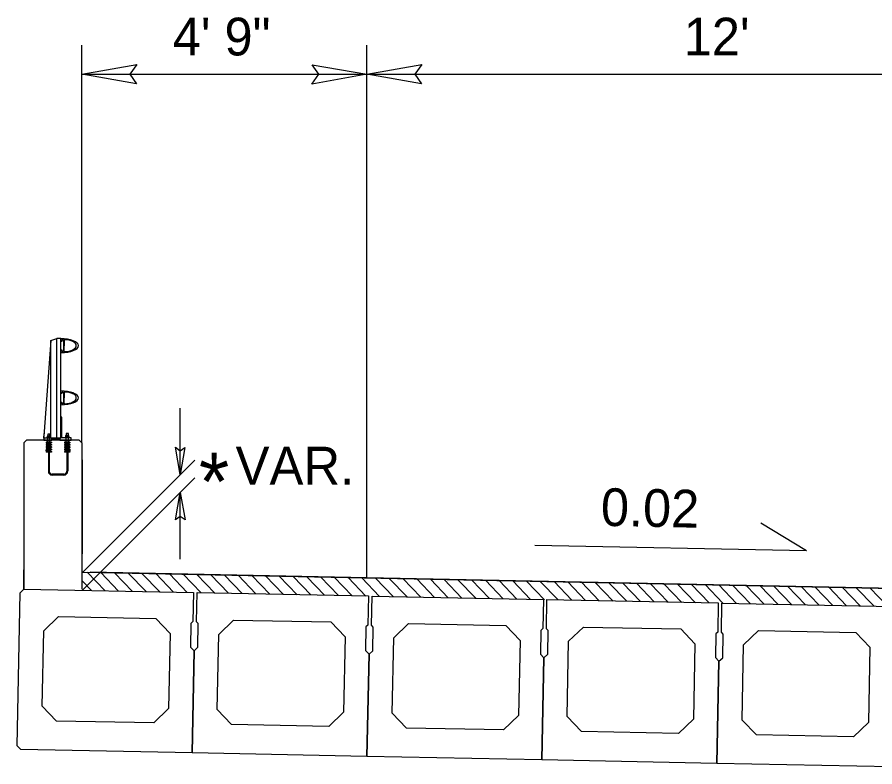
# Model space of a CAD drawing. Extents: x 573771 to 574316, y -53454 to -53190.
# Drawn here: x 574112.51 to 574141.94, y -53351.54 to -53325.81 of the extents above; entities that cross this region are included whole.
import ezdxf

# ---------------------------------------------------------------- set-up
doc = ezdxf.new("R2010")
doc.units = 0
for name, color, linetype in [('Default', 7, 'Continuous'), ('Typical Pavement Slope CELL', 7, 'Continuous'), ('Typical Pavement Slope Information CELL', 7, 'Continuous'), ('Typical Shoulder Slope CELL', 7, 'Continuous'), ('Typical Terminator CELL', 7, 'Continuous'), ('Typical Text Grade Point CELL', 7, 'Continuous')]:
    doc.layers.add(name, color=color, linetype=linetype)

msp = doc.modelspace()

# ---------------------------------------------------------------- linework, layer by layer
at = {"layer": 'Default'}
for p, q in [((574113.663, -53336.907), (574113.87, -53336.839)), ((574114.007, -53336.839), (574113.87, -53336.839)), ((574113.87, -53340.257), (574113.87, -53336.839)), ((574114.007, -53340.257), (574114.007, -53336.839)), ((574113.663, -53336.907), (574113.425, -53340.189)), ((574113.663, -53340.257), (574113.663, -53336.907)), ((574114.121, -53336.896), (574114.121, -53337.082)), ((574114.121, -53337.267), (574114.121, -53337.082)), ((574114.121, -53338.688), (574114.121, -53338.873)), ((574114.121, -53339.059), (574114.121, -53338.873)), ((574112.741, -53340.414), (574112.83, -53340.326)), ((574114.642, -53340.326), (574112.83, -53340.326)), ((574113.425, -53340.257), (574113.425, -53340.189)), ((574113.431, -53340.151), (574113.431, -53340.091)), ((574113.557, -53340.409), (574113.557, -53340.257)), ((574113.636, -53340.119), (574113.558, -53340.119)), ((574113.558, -53340.119), (574113.558, -53340.183)), ((574113.635, -53340.409), (574113.635, -53340.257)), ((574113.636, -53340.183), (574113.636, -53340.119)), ((574114.187, -53340.391), (574114.187, -53340.24)), ((574114.269, -53340.101), (574114.191, -53340.101)), ((574114.191, -53340.101), (574114.191, -53340.166)), ((574114.269, -53340.166), (574114.269, -53340.101)), ((574114.273, -53340.391), (574114.273, -53340.24)), ((574114.642, -53340.326), (574114.731, -53340.414)), ((574112.741, -53340.414), (574112.741, -53345.438)), ((574113.686, -53340.391), (574113.504, -53340.391)), ((574113.686, -53340.412), (574113.504, -53340.412)), ((574113.579, -53340.472), (574113.504, -53340.472)), ((574113.579, -53340.492), (574113.504, -53340.492)), ((574113.579, -53340.553), (574113.504, -53340.553)), ((574113.579, -53340.573), (574113.504, -53340.573)), ((574113.579, -53340.633), (574113.504, -53340.633)), ((574113.579, -53340.653), (574113.504, -53340.653)), ((574113.579, -53340.432), (574113.544, -53340.432)), ((574113.579, -53340.452), (574113.544, -53340.452)), ((574113.579, -53340.513), (574113.544, -53340.513)), ((574113.579, -53340.533), (574113.544, -53340.533)), ((574113.579, -53340.593), (574113.544, -53340.593)), ((574113.579, -53340.613), (574113.544, -53340.613)), ((574113.579, -53340.674), (574113.544, -53340.674)), ((574113.61, -53340.432), (574113.579, -53340.432)), ((574113.579, -53340.432), (574113.579, -53341.395)), ((574113.645, -53340.432), (574113.61, -53340.432)), ((574113.61, -53340.432), (574113.61, -53341.395)), ((574113.645, -53340.452), (574113.61, -53340.452)), ((574113.686, -53340.472), (574113.61, -53340.472)), ((574113.686, -53340.492), (574113.61, -53340.492)), ((574113.645, -53340.513), (574113.61, -53340.513)), ((574113.645, -53340.533), (574113.61, -53340.533)), ((574113.686, -53340.553), (574113.61, -53340.553)), ((574113.686, -53340.573), (574113.61, -53340.573)), ((574113.645, -53340.593), (574113.61, -53340.593)), ((574113.645, -53340.613), (574113.61, -53340.613)), ((574113.686, -53340.633), (574113.61, -53340.633)), ((574113.686, -53340.653), (574113.61, -53340.653)), ((574113.645, -53340.674), (574113.61, -53340.674)), ((574114.318, -53340.391), (574114.136, -53340.391)), ((574114.318, -53340.412), (574114.136, -53340.412)), ((574114.212, -53340.472), (574114.136, -53340.472)), ((574114.212, -53340.492), (574114.136, -53340.492)), ((574114.212, -53340.553), (574114.136, -53340.553)), ((574114.212, -53340.573), (574114.136, -53340.573)), ((574114.212, -53340.633), (574114.136, -53340.633)), ((574114.212, -53340.653), (574114.136, -53340.653)), ((574114.212, -53340.432), (574114.177, -53340.432)), ((574114.212, -53340.452), (574114.177, -53340.452)), ((574114.212, -53340.513), (574114.177, -53340.513)), ((574114.212, -53340.533), (574114.177, -53340.533)), ((574114.212, -53340.593), (574114.177, -53340.593)), ((574114.212, -53340.613), (574114.177, -53340.613)), ((574114.212, -53340.674), (574114.177, -53340.674)), ((574114.243, -53340.432), (574114.212, -53340.432)), ((574114.212, -53340.432), (574114.212, -53341.395)), ((574114.278, -53340.432), (574114.243, -53340.432)), ((574114.243, -53340.432), (574114.243, -53341.395)), ((574114.278, -53340.452), (574114.243, -53340.452)), ((574114.318, -53340.472), (574114.243, -53340.472)), ((574114.318, -53340.492), (574114.243, -53340.492)), ((574114.278, -53340.513), (574114.243, -53340.513)), ((574114.278, -53340.533), (574114.243, -53340.533)), ((574114.318, -53340.553), (574114.243, -53340.553)), ((574114.318, -53340.573), (574114.243, -53340.573)), ((574114.278, -53340.593), (574114.243, -53340.593)), ((574114.278, -53340.613), (574114.243, -53340.613)), ((574114.318, -53340.633), (574114.243, -53340.633)), ((574114.318, -53340.653), (574114.243, -53340.653)), ((574114.278, -53340.674), (574114.243, -53340.674)), ((574114.731, -53340.414), (574114.731, -53345.438)), ((574113.579, -53340.714), (574113.504, -53340.714)), ((574113.579, -53340.734), (574113.504, -53340.734)), ((574113.579, -53340.694), (574113.544, -53340.694)), ((574113.645, -53340.694), (574113.61, -53340.694)), ((574113.686, -53340.714), (574113.61, -53340.714)), ((574113.686, -53340.734), (574113.61, -53340.734)), ((574114.212, -53340.714), (574114.136, -53340.714)), ((574114.212, -53340.734), (574114.136, -53340.734)), ((574114.212, -53340.694), (574114.177, -53340.694)), ((574114.278, -53340.694), (574114.243, -53340.694)), ((574114.318, -53340.714), (574114.243, -53340.714)), ((574114.318, -53340.734), (574114.243, -53340.734)), ((574114.743, -53340.998), (574114.743, -53344.231)), ((574114.116, -53341.491), (574113.707, -53341.491)), ((574114.116, -53341.522), (574113.707, -53341.522)), ((574112.744, -53344.584), (574112.744, -53342.453)), ((574112.743, -53345.438), (574112.743, -53344.771)), ((574114.756, -53344.856), (574182.408, -53346.215)), ((574115.526, -53345.497), (574114.914, -53344.86)), ((574115.992, -53345.506), (574115.379, -53344.869)), ((574116.463, -53345.516), (574115.851, -53344.878)), ((574116.934, -53345.525), (574116.322, -53344.888)), ((574117.405, -53345.535), (574116.793, -53344.897)), ((574117.877, -53345.544), (574117.264, -53344.907)), ((574118.348, -53345.554), (574117.736, -53344.916)), ((574118.819, -53345.563), (574118.207, -53344.926)), ((574119.291, -53345.573), (574118.678, -53344.935)), ((574119.762, -53345.582), (574119.15, -53344.945)), ((574120.233, -53345.591), (574119.621, -53344.954)), ((574120.705, -53345.601), (574120.092, -53344.964)), ((574121.176, -53345.61), (574120.564, -53344.973)), ((574121.647, -53345.62), (574121.035, -53344.982)), ((574122.119, -53345.629), (574121.506, -53344.992)), ((574122.59, -53345.639), (574121.978, -53345.001)), ((574123.061, -53345.648), (574122.449, -53345.011)), ((574123.532, -53345.658), (574122.92, -53345.02)), ((574124.004, -53345.667), (574123.391, -53345.03)), ((574124.475, -53345.677), (574123.863, -53345.039)), ((574124.946, -53345.686), (574124.334, -53345.049)), ((574125.418, -53345.696), (574124.805, -53345.058)), ((574125.889, -53345.705), (574125.277, -53345.068)), ((574126.36, -53345.714), (574125.748, -53345.077)), ((574126.832, -53345.724), (574126.219, -53345.087)), ((574115.064, -53345.488), (574114.753, -53345.163)), ((574127.303, -53345.733), (574126.691, -53345.096)), ((574127.774, -53345.743), (574127.162, -53345.105)), ((574128.246, -53345.752), (574127.633, -53345.115)), ((574128.717, -53345.762), (574128.105, -53345.124)), ((574129.188, -53345.771), (574128.576, -53345.134)), ((574129.659, -53345.781), (574129.047, -53345.143)), ((574130.131, -53345.79), (574129.518, -53345.153)), ((574130.602, -53345.8), (574129.99, -53345.162)), ((574131.073, -53345.809), (574130.461, -53345.172)), ((574131.545, -53345.819), (574130.932, -53345.181)), ((574132.016, -53345.828), (574131.404, -53345.191)), ((574132.487, -53345.837), (574131.875, -53345.2)), ((574132.959, -53345.847), (574132.346, -53345.21)), ((574133.43, -53345.856), (574132.818, -53345.219)), ((574133.901, -53345.866), (574133.289, -53345.228)), ((574134.373, -53345.875), (574133.76, -53345.238)), ((574134.844, -53345.885), (574134.232, -53345.247)), ((574135.315, -53345.894), (574134.703, -53345.257)), ((574135.787, -53345.904), (574135.174, -53345.266)), ((574136.258, -53345.913), (574135.646, -53345.276)), ((574136.729, -53345.923), (574136.117, -53345.285)), ((574137.2, -53345.932), (574136.588, -53345.295)), ((574137.672, -53345.942), (574137.059, -53345.304)), ((574138.143, -53345.951), (574137.531, -53345.314)), ((574138.614, -53345.96), (574138.002, -53345.323)), ((574139.086, -53345.97), (574138.473, -53345.333)), ((574139.557, -53345.979), (574138.945, -53345.342)), ((574140.028, -53345.989), (574139.416, -53345.351)), ((574140.5, -53345.998), (574139.887, -53345.361)), ((574140.971, -53346.008), (574140.359, -53345.37)), ((574141.442, -53346.017), (574140.83, -53345.38)), ((574141.914, -53346.027), (574141.301, -53345.389)), ((574142.385, -53346.036), (574141.773, -53345.399))]:
    msp.add_line(p, q, dxfattribs=at)
for points in [[(574114.007, -53337.318), (574114.007, -53337.23), (574114.044, -53337.23), (574114.044, -53337.244), (574114.04, -53337.244), (574114.04, -53337.282), (574114.099, -53337.282), (574114.106, -53337.224), (574114.106, -53337.082), (574114.106, -53336.939), (574114.099, -53336.881), (574114.04, -53336.881), (574114.04, -53336.919), (574114.044, -53336.919), (574114.044, -53336.934), (574114.007, -53336.934), (574114.007, -53336.844)], [(574114.007, -53339.11), (574114.007, -53339.021), (574114.044, -53339.021), (574114.044, -53339.036), (574114.04, -53339.036), (574114.04, -53339.073), (574114.099, -53339.073), (574114.106, -53339.016), (574114.106, -53338.873), (574114.106, -53338.73), (574114.099, -53338.673), (574114.04, -53338.673), (574114.04, -53338.71), (574114.044, -53338.71), (574114.044, -53338.725), (574114.007, -53338.725), (574114.007, -53338.636)], [(574114.357, -53340.326), (574114.357, -53340.24), (574114.041, -53340.24), (574114.041, -53339.539), (574114.007, -53339.539), (574114.007, -53340.257), (574113.441, -53340.257), (574113.441, -53340.207), (574113.425, -53340.207), (574113.425, -53340.326), (574113.698, -53340.326), (574113.698, -53340.278), (574113.973, -53340.278), (574113.973, -53340.326), (574114.357, -53340.326)], [(574113.674, -53340.258), (574113.674, -53340.243), (574113.597, -53340.243), (574113.519, -53340.243), (574113.519, -53340.258)], [(574113.654, -53340.243), (574113.654, -53340.193), (574113.645, -53340.183), (574113.549, -53340.183), (574113.539, -53340.193), (574113.539, -53340.243), (574113.654, -53340.243), (574113.616, -53340.243), (574113.616, -53340.193), (574113.626, -53340.183), (574113.616, -53340.193), (574113.607, -53340.183), (574113.587, -53340.183), (574113.577, -53340.193), (574113.577, -53340.243), (574113.577, -53340.193), (574113.567, -53340.183)], [(574114.309, -53340.241), (574114.309, -53340.225), (574114.231, -53340.225), (574114.153, -53340.225), (574114.153, -53340.241)], [(574114.288, -53340.226), (574114.288, -53340.176), (574114.279, -53340.166), (574114.182, -53340.166), (574114.172, -53340.176), (574114.172, -53340.226), (574114.288, -53340.226), (574114.249, -53340.226), (574114.249, -53340.176), (574114.259, -53340.166), (574114.249, -53340.176), (574114.24, -53340.166), (574114.22, -53340.166), (574114.21, -53340.176), (574114.21, -53340.226), (574114.21, -53340.176), (574114.201, -53340.166)], [(574113.504, -53340.391), (574113.504, -53340.412), (574113.544, -53340.432), (574113.544, -53340.452), (574113.504, -53340.472), (574113.504, -53340.492), (574113.544, -53340.513), (574113.544, -53340.533), (574113.504, -53340.553), (574113.504, -53340.573), (574113.544, -53340.593), (574113.544, -53340.613), (574113.504, -53340.633), (574113.504, -53340.653), (574113.544, -53340.674), (574113.544, -53340.694), (574113.504, -53340.714), (574113.504, -53340.734)], [(574113.686, -53340.391), (574113.686, -53340.412), (574113.646, -53340.432), (574113.646, -53340.452), (574113.686, -53340.472), (574113.686, -53340.492), (574113.646, -53340.513), (574113.646, -53340.533), (574113.686, -53340.553), (574113.686, -53340.573), (574113.646, -53340.593), (574113.646, -53340.613), (574113.686, -53340.633), (574113.686, -53340.653), (574113.646, -53340.674), (574113.646, -53340.694), (574113.686, -53340.714), (574113.686, -53340.734)], [(574114.136, -53340.391), (574114.136, -53340.412), (574114.177, -53340.432), (574114.177, -53340.452), (574114.136, -53340.472), (574114.136, -53340.492), (574114.177, -53340.513), (574114.177, -53340.533), (574114.136, -53340.553), (574114.136, -53340.573), (574114.177, -53340.593), (574114.177, -53340.613), (574114.136, -53340.633), (574114.136, -53340.653), (574114.177, -53340.674), (574114.177, -53340.694), (574114.136, -53340.714), (574114.136, -53340.734)], [(574114.319, -53340.391), (574114.319, -53340.412), (574114.278, -53340.432), (574114.278, -53340.452), (574114.319, -53340.472), (574114.319, -53340.492), (574114.278, -53340.513), (574114.278, -53340.533), (574114.319, -53340.553), (574114.319, -53340.573), (574114.278, -53340.593), (574114.278, -53340.613), (574114.319, -53340.633), (574114.319, -53340.653), (574114.278, -53340.674), (574114.278, -53340.694), (574114.319, -53340.714), (574114.319, -53340.734)]]:
    msp.add_lwpolyline(points, dxfattribs=at)
for points in [[(574112.509, -53350.814), (574112.614, -53345.56), (574112.741, -53345.438), (574118.558, -53345.554), (574118.538, -53346.555), (574118.474, -53346.616), (574118.458, -53347.429), (574118.58, -53347.556), (574118.51, -53351.059), (574112.632, -53350.941)], [(574118.51, -53351.059), (574118.58, -53347.556), (574118.708, -53347.434), (574118.724, -53346.621), (574118.663, -53346.557), (574118.683, -53345.557), (574124.562, -53345.674), (574124.542, -53346.674), (574124.478, -53346.736), (574124.462, -53347.549), (574124.584, -53347.676), (574124.514, -53351.179)], [(574124.514, -53351.179), (574124.584, -53347.676), (574124.712, -53347.554), (574124.728, -53346.741), (574124.667, -53346.677), (574124.687, -53345.676), (574130.566, -53345.794), (574130.546, -53346.794), (574130.482, -53346.856), (574130.466, -53347.669), (574130.588, -53347.796), (574130.518, -53351.299)], [(574130.518, -53351.299), (574130.588, -53347.796), (574130.716, -53347.674), (574130.732, -53346.861), (574130.671, -53346.797), (574130.691, -53345.796), (574136.57, -53345.914), (574136.55, -53346.914), (574136.486, -53346.975), (574136.47, -53347.789), (574136.592, -53347.916), (574136.522, -53351.418)], [(574136.522, -53351.418), (574136.592, -53347.916), (574136.72, -53347.794), (574136.736, -53346.98), (574136.675, -53346.917), (574136.695, -53345.916), (574142.574, -53346.034), (574142.554, -53347.034), (574142.49, -53347.095), (574142.474, -53347.908), (574142.596, -53348.036), (574142.526, -53351.538)], [(574113.861, -53349.965), (574113.37, -53349.455), (574113.422, -53346.87), (574113.932, -53346.379), (574117.268, -53346.446), (574117.758, -53346.956), (574117.707, -53349.541), (574117.196, -53350.031)], [(574119.865, -53350.085), (574119.374, -53349.574), (574119.426, -53346.99), (574119.936, -53346.499), (574123.272, -53346.566), (574123.762, -53347.076), (574123.711, -53349.661), (574123.2, -53350.151)], [(574125.869, -53350.205), (574125.378, -53349.694), (574125.43, -53347.109), (574125.94, -53346.619), (574129.276, -53346.686), (574129.766, -53347.196), (574129.714, -53349.781), (574129.204, -53350.271)], [(574131.873, -53350.325), (574131.382, -53349.814), (574131.434, -53347.229), (574131.944, -53346.739), (574135.28, -53346.806), (574135.77, -53347.316), (574135.718, -53349.901), (574135.208, -53350.391)], [(574137.877, -53350.444), (574137.386, -53349.934), (574137.438, -53347.349), (574137.948, -53346.859), (574141.284, -53346.925), (574141.774, -53347.436), (574141.722, -53350.021), (574141.212, -53350.511)]]:
    msp.add_lwpolyline(points, close=True, dxfattribs=at)
for centre in [(574113.52, -53340.684), (574114.302, -53340.684)]:
    msp.add_circle(centre, 0.0151, dxfattribs=at)
for centre, radius, start, end in [((574114.136, -53336.896), 0.0142, 90, 180), ((574114.136, -53337.267), 0.0142, 180, 270), ((574114.136, -53338.687), 0.0142, 90, 180), ((574114.136, -53339.059), 0.0142, 180, 270), ((574113.707, -53341.395), 0.127, 180, 270), ((574113.707, -53341.395), 0.0969, 180, 270), ((574114.115, -53341.395), 0.0969, 270, 0), ((574114.115, -53341.395), 0.127, 270, 0)]:
    msp.add_arc(centre, radius, start, end, dxfattribs=at)
for centre, major_axis, ratio, start_param, end_param in [((574114.007, -53337.081), (0.607, 0), 0.39036, 6.282787, 7.853967), ((574114.007, -53337.081), (0.607, 0), 0.39036, 4.712404, 6.282787), ((574114.136, -53337.081), (0.403, 0), 0.495501, 6.282718, 7.853881), ((574114.136, -53337.081), (0.403, 0), 0.495501, 4.712489, 6.282718), ((574114.007, -53338.873), (0.607, 0), 0.39036, 6.282787, 7.853967), ((574114.007, -53338.873), (0.607, 0), 0.39036, 4.712404, 6.282787), ((574114.136, -53338.873), (0.403, 0), 0.495501, 6.282718, 7.853881), ((574114.136, -53338.873), (0.403, 0), 0.495501, 4.712489, 6.282718)]:
    msp.add_ellipse(centre, major_axis=major_axis, ratio=ratio, start_param=start_param, end_param=end_param, dxfattribs=at)
at = {"layer": 'Typical Pavement Slope CELL'}
msp.add_line((574148.511, -53345.534), (574124.52, -53345.054), dxfattribs=at)
at = {"layer": 'Typical Pavement Slope Information CELL'}
for p, q in [((574114.731, -53340.414), (574114.731, -53326.768)), ((574124.511, -53345.014), (574124.511, -53326.768)), ((574114.731, -53327.768), (574124.511, -53327.768)), ((574124.511, -53327.768), (574148.511, -53327.768)), ((574118.106, -53341.509), (574118.106, -53339.224)), ((574114.759, -53344.856), (574118.606, -53341.009)), ((574114.75, -53345.478), (574118.606, -53341.622)), ((574118.106, -53344.407), (574118.106, -53342.122)), ((574139.592, -53344.124), (574138.026, -53343.178)), ((574139.592, -53344.124), (574130.271, -53343.938))]:
    msp.add_line(p, q, dxfattribs=at)
at = {"layer": 'Typical Shoulder Slope CELL'}
msp.add_line((574124.52, -53345.054), (574115.011, -53344.859), dxfattribs=at)
at = {"layer": 'Typical Terminator CELL'}
for points in [[(574116.605, -53328.091), (574114.731, -53327.768), (574116.616, -53327.435), (574116.376, -53327.768)], [(574122.637, -53327.445), (574124.511, -53327.768), (574122.626, -53328.101), (574122.866, -53327.768)], [(574126.386, -53328.091), (574124.511, -53327.768), (574126.397, -53327.435), (574126.157, -53327.768)], [(574118.267, -53340.572), (574118.106, -53341.509), (574117.939, -53340.567), (574118.106, -53340.687)], [(574117.944, -53343.059), (574118.106, -53342.122), (574118.273, -53343.064), (574118.106, -53342.944)]]:
    msp.add_lwpolyline(points, close=True, dxfattribs=at)

# ---------------------------------------------------------------- texts
at = {"layer": 'Typical Pavement Slope Information CELL'}
for s, p in [('4\' 9"', (574117.85, -53327.12)), ("12'", (574135.386, -53327.12))]:
    msp.add_text(s, height=1.2952, dxfattribs=at).set_placement(p)
msp.add_text('0.02', height=1.2952, rotation=358.8543, dxfattribs=at).set_placement((574132.532, -53343.264))
at = {"layer": 'Typical Text Grade Point CELL'}
for s, height, p in [('VAR.', 1.305, (574120.005, -53341.855)), ('* ', 2, (574118.746, -53342.75))]:
    msp.add_text(s, height=height, dxfattribs=at).set_placement(p)

doc.saveas('drawing.dxf')
